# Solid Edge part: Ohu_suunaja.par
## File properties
Author: Georg
Template: Iso Part.par
Last saved by: Georg
Revision: 2
Application: Solid Edge
Accuracy: 0,990
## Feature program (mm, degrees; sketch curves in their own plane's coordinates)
sketch for "unnamed Protrusion 1" plane through (0, 0, 0) normal (1, 0, 0) x-axis (0, 1, 0)
  line (-50.3038, -53.6377) -> (-43.3038, -53.6377)
  line (-43.3038, -53.6377) -> (-43.3038, -39.6377)
  line (-43.3038, -39.6377) -> (-50.3038, -39.6377)
  line (-50.3038, -39.6377) -> (-50.3038, -53.6377)
  dimension (linear) = 43.3038
  dimension (linear) = 43.3038
extrude "unnamed Protrusion 1" add finite 30 along +normal
sketch for "ExtrudedCutout_1" plane through (15, -46.8038, -39.6377) normal (0, 0, 1) x-axis (1, 0, 0)
  line (10.3746, 3.5) -> (15, -3.5)
extrude "ExtrudedCutout_1" cut finite 30.2234 along -normal
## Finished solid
Body 1: solid body, 6 faces, 12 edges, 8 vertices.
  Faces by surface: plane 6
  Edges by curve: line 12
Bounding box of the edges (mm): 30.000 x 7.000 x 14.000, from (0, -50.3038, -53.6377) to (30, -43.3038, -39.6377).
Planar faces by outward normal: +y 1, +z 1, -x 1, -y 1, -z 1, oblique 1
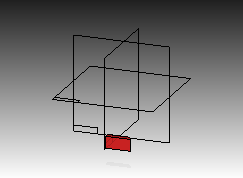
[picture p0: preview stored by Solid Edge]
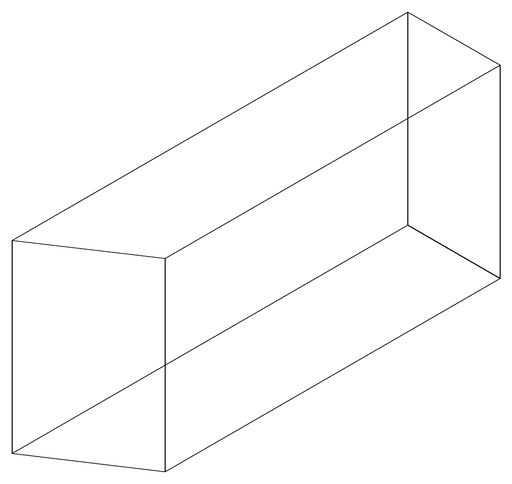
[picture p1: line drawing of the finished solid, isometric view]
